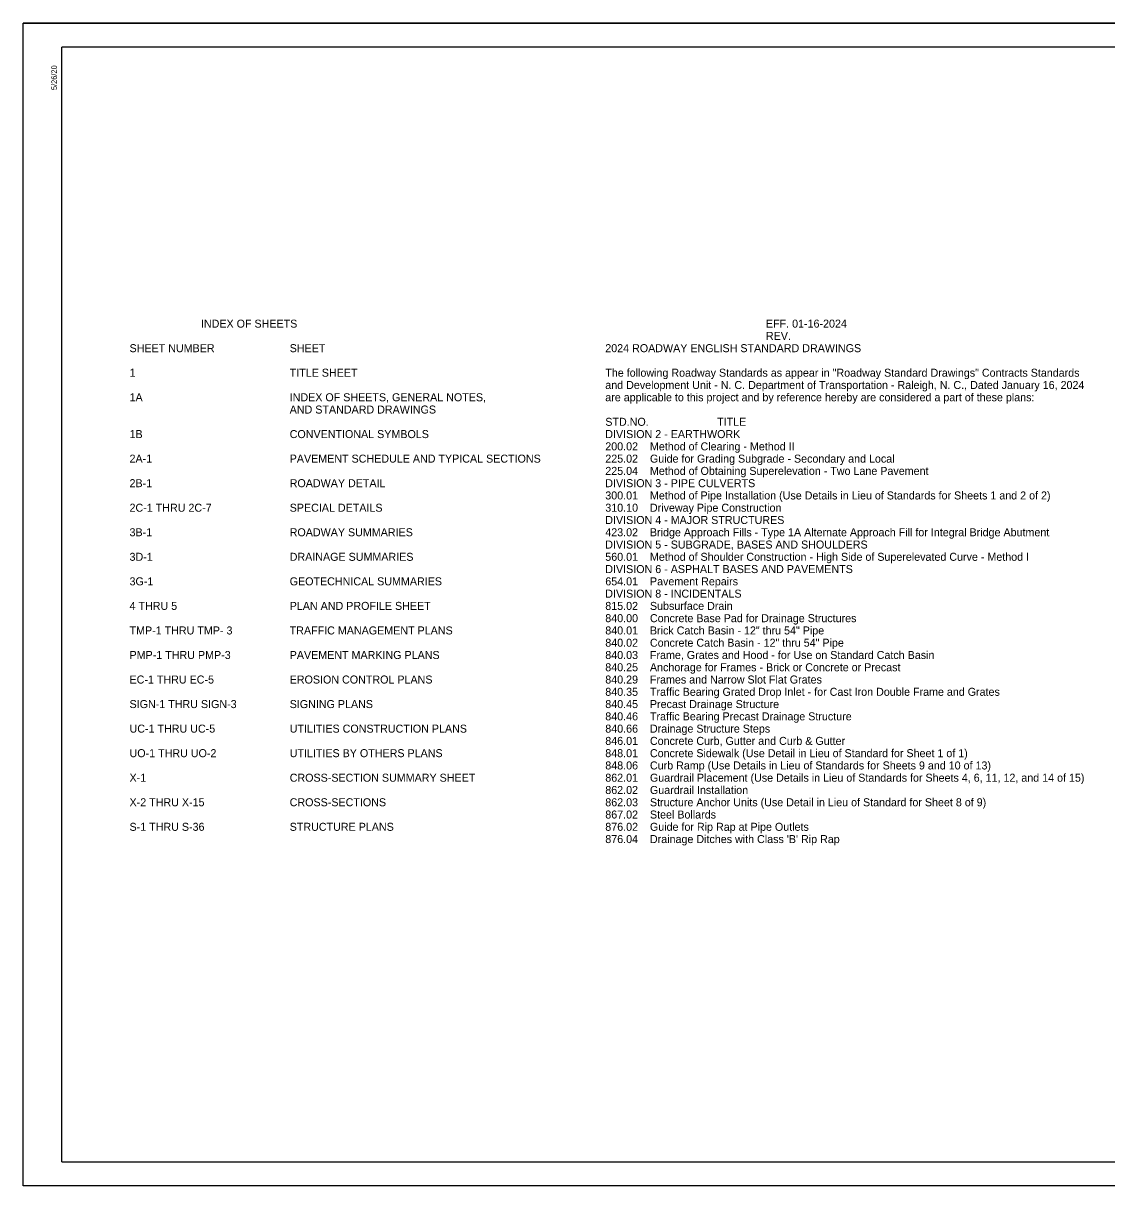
# Model space of a CAD drawing. Extents: x 1184048.9 to 1184122, y 1246638.9 to 1246660.6.
# Drawn here: x 1184081.36 to 1184101.66, y 1246638.86 to 1246660.65 of the extents above; entities that cross this region are included whole.
import ezdxf

# ---------------------------------------------------------------- set-up
doc = ezdxf.new("R2010")
doc.units = 0
for name, color, linetype in [('Sheet Data Field CELL', 7, 'Continuous'), ('Sheet Plan CELL', 7, 'Continuous'), ('Sheet Plot Border Outside CELL', 7, 'Continuous'), ('z - Construction', 7, 'Continuous')]:
    doc.layers.add(name, color=color, linetype=linetype)

msp = doc.modelspace()

# ---------------------------------------------------------------- linework, layer by layer
at = {"layer": 'Sheet Plan CELL'}
for p, q in [((1184114.767, 1246660.2), (1184082.086, 1246660.2)), ((1184082.086, 1246639.305), (1184082.086, 1246660.2)), ((1184082.086, 1246639.305), (1184114.766, 1246639.305))]:
    msp.add_line(p, q, dxfattribs=at)
at = {"layer": 'Sheet Plot Border Outside CELL'}
msp.add_lwpolyline([(1184081.364, 1246660.645), (1184115.034, 1246660.645), (1184115.034, 1246638.859), (1184081.364, 1246638.859)], close=True, dxfattribs=at)
at = {"layer": 'z - Construction'}
msp.add_line((1184115.034, 1246660.645), (1184081.364, 1246660.645), dxfattribs=at)

# ---------------------------------------------------------------- texts
at = {"layer": 'Sheet Data Field CELL'}
for s, p in [('                        INDEX OF SHEETS ', (1184083.355, 1246654.941)), ('                                                      EFF. 01-16-2024', (1184092.267, 1246654.941)), ('                                                      REV. ', (1184092.267, 1246654.711)), ('SHEET NUMBER                 ', (1184083.355, 1246654.481)), ('SHEET   ', (1184086.355, 1246654.481)), ('2024 ROADWAY ENGLISH STANDARD DRAWINGS', (1184092.267, 1246654.481)), ('1                       ', (1184083.355, 1246654.021)), ('TITLE SHEET', (1184086.355, 1246654.021)), ('The following Roadway Standards as appear in "Roadway Standard Drawings" Contracts Standards', (1184092.267, 1246654.021)), ('and Development Unit - N. C. Department of Transportation - Raleigh, N. C., Dated January 16, 2024', (1184092.267, 1246653.791)), ('are applicable to this project and by reference hereby are considered a part of these plans:', (1184092.267, 1246653.561)), ('1A                      ', (1184083.355, 1246653.561)), ('INDEX OF SHEETS, GENERAL NOTES,', (1184086.355, 1246653.561)), ('AND STANDARD DRAWINGS', (1184086.355, 1246653.331)), ('STD.NO.                       TITLE', (1184092.267, 1246653.101)), ('1B                      ', (1184083.355, 1246652.871)), ('CONVENTIONAL SYMBOLS ', (1184086.355, 1246652.871)), ('DIVISION 2 - EARTHWORK', (1184092.267, 1246652.871)), ('200.02    Method of Clearing - Method II', (1184092.267, 1246652.641)), ('2A-1', (1184083.355, 1246652.411)), ('PAVEMENT SCHEDULE AND TYPICAL SECTIONS', (1184086.355, 1246652.411)), ('225.02    Guide for Grading Subgrade - Secondary and Local', (1184092.267, 1246652.411)), ('225.04    Method of Obtaining Superelevation - Two Lane Pavement', (1184092.267, 1246652.181)), ('2B-1', (1184083.355, 1246651.951)), ('ROADWAY DETAIL', (1184086.355, 1246651.951)), ('DIVISION 3 - PIPE CULVERTS', (1184092.267, 1246651.951)), ('300.01    Method of Pipe Installation (Use Details in Lieu of Standards for Sheets 1 and 2 of 2)', (1184092.267, 1246651.721)), ('2C-1 THRU 2C-7           ', (1184083.355, 1246651.491)), ('SPECIAL DETAILS', (1184086.355, 1246651.491)), ('310.10    Driveway Pipe Construction', (1184092.267, 1246651.491)), ('DIVISION 4 - MAJOR STRUCTURES', (1184092.267, 1246651.261)), ('3B-1 ', (1184083.355, 1246651.031)), ('ROADWAY SUMMARIES', (1184086.355, 1246651.031)), ('423.02    Bridge Approach Fills - Type 1A Alternate Approach Fill for Integral Bridge Abutment', (1184092.267, 1246651.031)), ('DIVISION 5 - SUBGRADE, BASES AND SHOULDERS', (1184092.267, 1246650.801)), ('3D-1', (1184083.355, 1246650.571)), ('DRAINAGE SUMMARIES', (1184086.355, 1246650.571)), ('560.01    Method of Shoulder Construction - High Side of Superelevated Curve - Method I', (1184092.267, 1246650.571)), ('DIVISION 6 - ASPHALT BASES AND PAVEMENTS', (1184092.267, 1246650.341)), ('3G-1', (1184083.355, 1246650.111)), ('GEOTECHNICAL SUMMARIES', (1184086.355, 1246650.111)), ('654.01    Pavement Repairs', (1184092.267, 1246650.111)), ('DIVISION 8 - INCIDENTALS', (1184092.267, 1246649.881)), ('4 THRU 5                ', (1184083.355, 1246649.651)), ('PLAN AND PROFILE SHEET', (1184086.355, 1246649.651)), ('815.02    Subsurface Drain', (1184092.267, 1246649.651)), ('840.00    Concrete Base Pad for Drainage Structures', (1184092.267, 1246649.421)), ('TMP-1 THRU TMP- 3        ', (1184083.355, 1246649.191)), ('TRAFFIC MANAGEMENT PLANS', (1184086.355, 1246649.191)), ('840.01    Brick Catch Basin - 12" thru 54" Pipe', (1184092.267, 1246649.191)), ('840.02    Concrete Catch Basin - 12" thru 54" Pipe', (1184092.267, 1246648.961)), ('PMP-1 THRU PMP-3         ', (1184083.355, 1246648.731)), ('PAVEMENT MARKING PLANS', (1184086.355, 1246648.731)), ('840.03    Frame, Grates and Hood - for Use on Standard Catch Basin', (1184092.267, 1246648.731)), ('840.25    Anchorage for Frames - Brick or Concrete or Precast', (1184092.267, 1246648.501)), ('EC-1 THRU EC-5           ', (1184083.355, 1246648.271)), ('EROSION CONTROL PLANS', (1184086.355, 1246648.271)), ('840.29    Frames and Narrow Slot Flat Grates', (1184092.267, 1246648.271)), ('840.35    Traffic Bearing Grated Drop Inlet - for Cast Iron Double Frame and Grates', (1184092.267, 1246648.041)), ('SIGN-1 THRU SIGN-3      ', (1184083.355, 1246647.811)), ('SIGNING PLANS', (1184086.355, 1246647.811)), ('840.45    Precast Drainage Structure', (1184092.267, 1246647.811)), ('840.46    Traffic Bearing Precast Drainage Structure', (1184092.267, 1246647.581)), ('UC-1 THRU UC-5           ', (1184083.355, 1246647.351)), ('UTILITIES CONSTRUCTION PLANS', (1184086.355, 1246647.351)), ('840.66    Drainage Structure Steps', (1184092.267, 1246647.351)), ('846.01    Concrete Curb, Gutter and Curb & Gutter', (1184092.267, 1246647.121)), ('UO-1 THRU UO-2', (1184083.355, 1246646.891)), ('UTILITIES BY OTHERS PLANS', (1184086.355, 1246646.891)), ('848.01    Concrete Sidewalk (Use Detail in Lieu of Standard for Sheet 1 of 1)', (1184092.267, 1246646.891)), ('848.06    Curb Ramp (Use Details in Lieu of Standards for Sheets 9 and 10 of 13)', (1184092.267, 1246646.661)), ('X-1', (1184083.355, 1246646.431)), ('CROSS-SECTION SUMMARY SHEET', (1184086.355, 1246646.431)), ('862.01    Guardrail Placement (Use Details in Lieu of Standards for Sheets 4, 6, 11, 12, and 14 of 15)', (1184092.267, 1246646.431)), ('862.02    Guardrail Installation', (1184092.267, 1246646.201)), ('X-2 THRU X-15             ', (1184083.355, 1246645.971)), ('CROSS-SECTIONS', (1184086.355, 1246645.971)), ('862.03    Structure Anchor Units (Use Detail in Lieu of Standard for Sheet 8 of 9)', (1184092.267, 1246645.971)), ('867.02    Steel Bollards', (1184092.267, 1246645.741)), ('S-1 THRU S-36             ', (1184083.355, 1246645.511)), ('STRUCTURE PLANS', (1184086.355, 1246645.511)), ('876.02    Guide for Rip Rap at Pipe Outlets', (1184092.267, 1246645.511)), ("876.04    Drainage Ditches with Class 'B' Rip Rap", (1184092.267, 1246645.281))]:
    msp.add_text(s, height=0.15, dxfattribs=at).set_placement(p)
at = {"layer": 'Sheet Plan CELL'}
msp.add_text('5/26/20', height=0.104, rotation=90, dxfattribs=at).set_placement((1184081.994, 1246659.393))

doc.saveas('drawing.dxf')
